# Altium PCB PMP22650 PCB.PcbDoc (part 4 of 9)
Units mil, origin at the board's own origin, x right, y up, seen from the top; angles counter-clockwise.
Board outline 11311 x 5233 mil, 8 copper layers (Layer 1, Layer 2, Layer 3, Layer 4, Layer 5, Layer 6, Layer 7, Layer 8), stack 88.6 mil thick; 633 components, 410 nets, 2503 pads, 1993 vias.
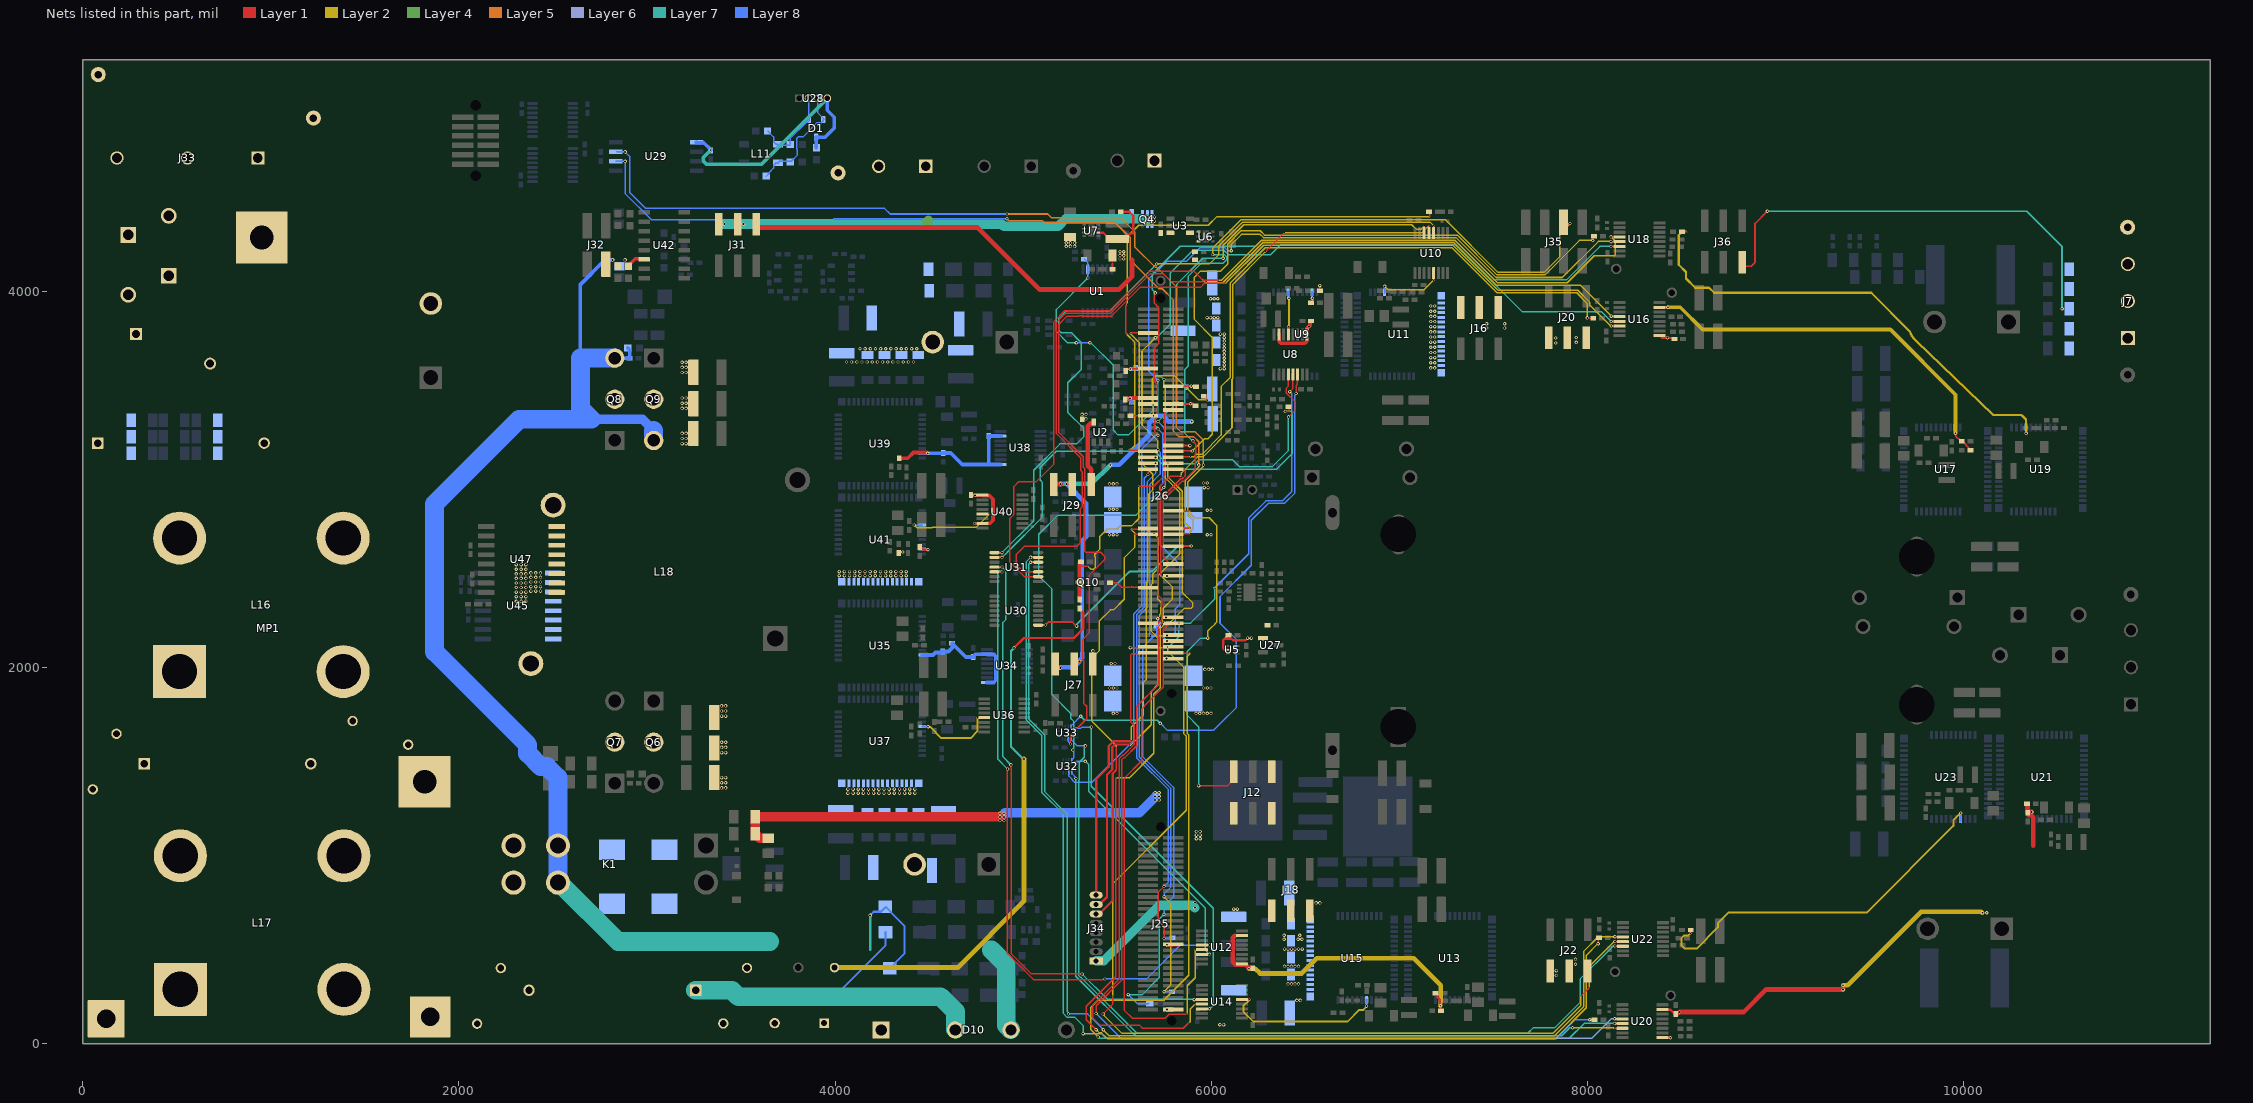
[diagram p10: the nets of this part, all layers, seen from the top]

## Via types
v1: diameter 18, hole 10, Layer 1 to Layer 8, 1759 vias
v2: diameter 8, hole 4, Layer 1 to Layer 2, 160 vias
v3: diameter 18, hole 10, Layer 1 to Layer 8, tented both sides, 34 vias
v4: diameter 8, hole 4, Layer 7 to Layer 8, 28 vias
v5: diameter 19.68, hole 7.87, Layer 1 to Layer 8, 8 vias
v6: diameter 118.11, hole 86.61, Layer 1 to Layer 8, 4 vias

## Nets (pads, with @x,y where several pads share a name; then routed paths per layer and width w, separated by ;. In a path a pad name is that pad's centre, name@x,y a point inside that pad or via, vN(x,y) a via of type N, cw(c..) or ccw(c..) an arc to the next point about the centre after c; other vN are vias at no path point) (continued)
5V_H_PFC_2: C185.1 C188.1 R113.2 U40.1 U40.7 U41.51 | length 430.8
  Layer 1 w8: R113.2@4337.63,2609.04 4337.63,2612.98 4340.44,2615.79 4358.21,2615.79 v1@4360,2614 ; v1@4493,2626 v1@4495,2624
  Layer 1 w12: C188.1@4448.27,2642.28 4454.08,2636.47 4458.02,2636.47 4466.89,2627.6 v1(4493.27,2627.6) ; v1(4741,2767) 4741.25,2767.25 4778.25,2767.25 U40.7@4779,2768
  Layer 1 w20: C185.1@4724,2918 4724.5,2917.5 U40.1@4782.7,2917.5 4784.13,2916.07 4819.48,2916.07 4839.5,2896.05 4839.5,2783.92 4824.51,2768.93 U40.7@4804.2,2768.93
  Layer 8 w12: U41.51@4463.27,2632.6 4468.27,2627.6 v1(4493.27,2627.6)
  other v1: 4359.1,2615.79 4744,2917
5V_L_A: C40.1 C43.1 R27.2 U8.1 U8.7 U9.51 | length 404.9
  Layer 1 w10: C43.1@6530,3941 6530.19,3941 6537,3947.81 v1(6537,3965) ; v1(6576,4032) 6576,4007 R27.2@6578,4005
  Layer 1 w20: U8.7@6358.98,3772.34 6360.41,3770.91 6360.41,3735.56 6370.62,3725.34 6374.48,3725.34 6374.72,3725.09 6497.08,3725.09 6507.55,3735.56 6507.55,3770.91 U8.1@6508.98,3772.34 6508.98,3805.31 v1@6517.27,3813.6 ; v1(6519.09,3814.57) 6525.14,3820.62 6525.14,3841.79 6526.95,3843.6 C40.1@6530.89,3843.6
  Layer 8 w10: v1@6517.94,3815.71 v1(6519.09,3814.57) ; U9.51@6536.03,3998.97 U9.51@6536.03,3997.68 ; v1(6537,3965) 6536.03,3965.97 U9.51@6536.03,3997.68 ; U9.51@6537.83,3999.48 U9.51@6536.03,3997.68
5V_L_B: C62.1 C65.1 R37.2 U12.1 U12.7 U13.51 | length 1671.1
  Layer 1 w12: 6126.56,576.05 U12.7@6162.57,576.05 ; R37.2@7195.89,269 7201.7,263.19 7201.7,249.3 7214.13,236.87 7214.13,213.43 7215.85,211.7 7215.85,204.15 7218.15,201.85 7218.15,178.15 7218,178 C65.1@7217,177
  Layer 1 w25: 6126.56,576.05 6123.68,576.05 6113.07,565.44 6113.07,436.65 6128.56,421.16 6182.02,421.16 6197.51,405.67 6219.95,405.67 6220.64,404.98 C62.1@6220.64,402.42
  Layer 2 w20: v1@7217.49,202.49 7218.5,203.5 7218.5,227.5 7220,229
  Layer 2 w25: v1(6200,400) 6234,400 6258.9,375.1 6480.55,375.1 6560.45,455 7075,455 7219,311 7219,230 7220,229
  Layer 8 w12: v1(7217,203) 7217.54,203.54 7217.54,233.46 U13.51@7217,234
5V_L_C: C84.1 C87.1 R47.2 U16.1 U16.7 U17.51 | length 2225.7
  Layer 1 w10: v1(9956,3247) 9957.53,3245.47 9957.53,3231.78 9983.31,3206 C87.1@9989,3206 ; C87.1@9989.65,3203.6 9993.58,3203.6 10026.14,3171.04 10026.14,3163.41 10032.95,3156.6 R47.2@10036.89,3156.6
  Layer 1 w12: U16.1@8382,3769 8396,3755 v1(8425,3755) 8426.62,3755 v1@8427,3754.62 ; U16.7@8382.3,3916.5 8382.55,3916.75 8424.75,3916.75 v1@8426,3918 ; v1@8427,3756 v1@8427,3754.62 ; C84.1@8463,3747 8456.19,3753.81 8427.81,3753.81 v1@8427,3754.62
  Layer 2 w20: v1(8427,3917) 8493,3917 8612,3798 9609.99,3798 9956,3451.99 v1(9956,3247)
  Layer 8 w12: U17.51@9954.86,3278.02 U17.51@9955.44,3277.44 ; v1(9956,3247) 9955.43,3247.57 U17.51@9955.43,3277.43 ; U17.51@9956,3278 U17.51@9955.44,3277.44 ; U17.51@9956.73,3276.15 U17.51@9955.44,3277.44
5V_L_D: C106.1 C109.1 R57.2 U20.1 U20.7 U21.51 | length 2270.7
  Layer 1 w12: U20.1@8393,33 8393.25,33.25 8440.75,33.25 v1(8441,33) ; U20.7@8398.3,183.5 8400.37,181.43 8441.37,181.43 8443.43,179.37 8443.94,179.37 C106.1@8461,162.32
  Layer 1 w25: C106.1@8468,160.38 8468,162.94 8468.69,163.63 8482.99,163.63 8486.17,166.81 8486.81,166.81 8490,170 8831,170 8951,290 v1@9360.26,290 ; C109.1@10339,1229.36 R57.2@10339,1275 ; C109.1@10339.27,1229.22 10339.27,1226.66 10350.2,1215.72 10358.53,1215.72 10369.08,1205.18 10369.08,1053.08 ; C109.1@10339.27,1229.36 10339.96,1230.05 10350.95,1230.05 10353.9,1233 v3(10361,1233)
  Layer 2 w25: v1(9359,312) 9382.26,312 9773.26,703 10093,703 v1@10098,698
  Layer 8 w10: v3@10363.1,1232.86 10364.6,1231.36 10364.6,1197.36 U21.51@10366.1,1195.86
  other v1: 8489,170 9359,289 10099.24,697.61 10122.24,697.61
5V_L_PFC_1: C148.1 C151.1 R98.2 U34.1 U34.7 U35.51 | length 657.6
  Layer 8 w20: U35.51@4463.12,2067.7 4519.69,2067.7 4533.13,2081.13 4569.46,2081.13 4571.27,2082.95 C151.1@4571.27,2086.88 4603.18,2086.88 4621.89,2105.59 R98.2@4621.89,2130.02 4625.83,2130.02 4627.64,2128.21 4627.64,2124.28 4694.41,2057.5 C148.1@4735.27,2057.5 4735.27,2061.44 4745.43,2071.6 4806.47,2071.6 U34.7@4806.97,2072.1 4808.4,2070.67 4843.75,2070.67 4854.21,2060.21 4854.21,1933.86 4842.5,1922.14 U34.1@4806.97,1922.1 U34.1@4806.97,1922.1
5V_L_PFC_2: C170.1 C173.1 R108.2 U38.1 U38.7 U39.51 | length 824.4
  Layer 1 w20: R108.2@4341.27,3114.22 4386.22,3114.22 4417,3145 4487.31,3145 v1(4492.12,3140.19)
  Layer 8 w20: U39.51@4463.12,3140.19 v1(4492.12,3140.19) 4572.83,3140.19 4574.65,3142 C173.1@4574.65,3142.51 4614.49,3142.51 4675.9,3081.1 4820.9,3081.1 ; U38.1@4878.97,3081.1 4820.9,3081.1 ; U38.7@4878.97,3231.1 4878.28,3231.79 4817.16,3231.79 C170.1@4816.47,3232.48 4816.47,3085.53 4820.9,3081.1
5V_PRI: C25.2 C26.2 C32.1 C33.2 C34.2 C37.1 C136.1 J12.5 J16.5 J18.5 J20.5 J22.5 J25.158 J25.180 J26.48 J26.84 J26.98 J26.112 J27.5 J29.5 J31.5 L2.2 R23.2 R25.2 U2.5 U3.3 U3.4 U5.2 U6.4 U6.6 U7.6 U27.1 | length 3606.2
  Layer 1 w10: v1(5758.27,2267.6) 5758.77,2268.1 5796.77,2268.1 J26.98@5797.27,2268.6 ; J26.112@5823.27,2047.6 J26.112@5823.53,2047.86
  Layer 1 w12: U7.6@5398.27,4314.6 5399.35,4313.52 5425.67,4313.52 5458.93,4280.26 L2.2@5500.27,4280.26 5541.61,4280.26 5569.9,4308.55 5584.5,4308.55 5584.5,4404.09 5564.06,4424.53 R23.2@5518.16,4424.53 ; R25.2@5474.83,4119.16 5474.83,4148.97 ; v1(5762,2050) 5762.94,2049.06 5812.94,2049.06 J26.112@5815,2047 ; v1(5763.27,2487.6) 5764,2488.33 5802.53,2488.33 J26.84@5803.27,2487.6 ; J26.48@5843.27,3182.6 5843.57,3182.29 5886.89,3182.29 5886.89,3181 v1(5886,3181) ; U5.2@6088.2,2095.29 6069.95,2095.29 6062.92,2102.32 6062.92,2147.95 6068.07,2153.1 ; C37.1@6092.2,2173.29 6088.27,2173.29 6068.07,2153.1 ; v1(6192.91,2157.72) 6181.18,2146 6115,2146 6107.9,2153.1 6068.07,2153.1
  Layer 1 w20: v1(5763.27,182.6) 5763.56,182.89 5797.11,182.89 J25.180@5797.27,183.05 ; v1(5763.27,527.6) J25.158@5828.27,527.6
  Layer 1 w25: J31.5@3577,4356 3577,4352.09 3588.49,4340.6 4757.4,4340.6 5087,4011 5506.67,4011 5578.27,4082.6 5578.27,4167.6 ; J29.5@5361.76,2978.64 5361.76,3055.4 5343.08,3074.08 5343.08,3284.21 5358.41,3299.55 U2.5@5375.18,3299.55
  Layer 5 w20: v1(5763.27,182.6) 5793.27,182.6 ; v1(5763.27,527.6) 5788.27,527.6
  other v1: 7834,364 7834,390 5920.2,1091.15 5940.27,1091.13 5920.2,1110.36 5940.27,1110.36 5920.2,1129.6 5940.27,1129.6 5370,2090 6212.59,2157.72 5333.27,3323.6 5313.27,3347.6 5333.27,3347.6 7830.73,3726.77 7830.73,3753.14 7559.27,3806.6 7559.27,3829.12 5514.27,4173.15 5534.34,4173.13 5514.27,4192.36 5534.34,4192.36 5514.27,4211.6 5534.34,4211.6
12V_PRI: C31.1 C214.1 J12.1 J12.2 J15.1 Q4.4 R17.2 R157.2 R158.2 U7.2 U7.3 | length 2338.5
  Layer 1 w50: C214.1@3644.27,1094.6 3597.57,1094.6 3585.76,1106.41 3574.93,1106.41 3574.34,1107 R158.2@3574.34,1117.83 R157.2@3574.34,1207.83 v1@4877.04,1207.83
  Layer 8 w50: 4886.92,1213.6 4901.61,1228.29 5616.23,1228.29 v1@5704.31,1316.36
  other v1: 4876.42,1188.15 4897.49,1188.13 4876.42,1207.36 4897.49,1207.36 4876.42,1226.6 4897.49,1226.6 5701.31,1297.15 5722.38,1297.13 5701.31,1316.36 5722.38,1316.36 5701.31,1335.6 5722.38,1335.6 5228.27,4240.67 5250.77,4240.67 5273.27,4240.67 5228.27,4258.85 5250.77,4258.85 5273.27,4258.85
12V_SW: J16.1 J16.3 J18.1 J18.3 J20.1 J20.3 J22.1 J22.3 J27.1 J27.3 J29.1 J29.3 J31.1 J31.3 J34.1 Q4.1 Q4.2 Q4.5 Q4.6 | length 5058.7
  Layer 1 w10: v1(5230,2978) 5267.87,2978 J29.3@5268.27,2977.6
  Layer 1 w20: J27.1@5173.27,2002.6 5177.5,1998.36 v1(5196.98,1998.36) ; J27.3@5273.27,2032.6 5275.11,2034.44 v1(5299.26,2034.44)
  Layer 1 w25: J29.1@5173.27,2977.6 v1(5198.27,2977.6)
  Layer 7 w25: v1(5230,2978) 5362.67,2978 v1(5462.27,3077.6)
  Layer 7 w50: 3399.19,4358.1 3513,4358.1 4886.9,4358.1 4896.91,4348.1 5186.64,4348.1 5226.14,4387.6 5649.48,4387.6 v1@5659.3,4377.78 ; J34.1@5387.63,441.44 5389.13,442.94 5427.92,442.94 5722.98,738 5898.87,738 v1(5912.27,724.6)
  Layer 8 w20: 5313.06,2078.24 5313.06,2675.06
  Layer 8 w25: v1@5198.27,2002.6 5267.42,2002.6 v1(5299.26,2034.44) ; v1(5198.27,2977.6) 5198.67,2978 v1(5230,2978) 5333.37,2874.63 5333.37,2695.37 5313.06,2675.06 ; v1@5298.27,2037.6 5313.06,2052.39 5313.06,2078.24 ; v1@5465.16,3079.49 5509.49,3079.49 5669.77,3239.77 5669.77,3301.77 5708,3340 5743.45,3340 5774.45,3309 v1(5896,3309)
  other v1: 7936,424 7936,450 6557,750 6576.69,750 5912.27,751.98 7939.73,3729.77 7939.73,3756.14 7464.27,3806.6 7464.27,3829.12 3411,4359 3513,4359 5659.3,4374.78 5678.53,4374.78 5697.77,4374.78 5659.3,4395.85 5678.53,4395.85 5697.77,4395.85
12VBatt-: C138.1 C140.2 D1.3 U28.4 U29.5 | length 1325.9
  Layer 7 w20: v1(3338.27,4752.6) 3298.27,4712.6 3298.27,4694.31 3315.48,4677.1 3608.92,4677.1 3958.27,5026.45 U28.4@3958.27,5027.6
  Layer 8 w20: U29.5@3263.27,4792.6 3264.08,4791.79 3301.64,4791.79 3338.27,4755.16 v1(3338.27,4752.6) C140.2@3338.27,4751.22 ; D1.3@3898.27,4817.6 3898.99,4816.88 3898.99,4765.81 C138.1@3899.7,4765.09 ; D1.3@3898.27,4820.35 3946.02,4820.35 3994.98,4869.31 3994.98,4927.21 3958.27,4963.93 U28.4@3958.27,5027.6
AC_L: C220.1 C222.2 D4.2 D6.2 D10.2 L17.1 U45.1 U45.2 U45.3 U45.4 U47.1 U47.2 U47.3 U47.4 | length 3747.3
  Layer 7 w100: C220.1@3258.09,285.63 3451.13,285.63 3485.25,251.51 4560.49,251.51 4639.97,172.03 ; D10.2@4639.97,78 4639.97,172.03 ; 4641,171 4639.97,172.03
  Layer 8 w8: C220.1@3258.09,285.63 3285.12,258.6 D6.2@4291.08,258.6
  Layer 8 w10: C220.1@3258.09,285.63 4028.63,285.63 4267.65,524.65 D4.2@4267.65,594.8
  other v1: 2304.27,2353.97 2330.27,2353.97 2355.27,2353.97 2304.27,2378.24 2330.27,2378.24 2355.27,2378.24 2304.27,2402.51 2330.27,2402.51 2355.27,2402.51 2382.27,2407.6 2408.27,2407.6 2433.27,2407.6 2304.27,2426.79 2330.27,2426.79 2355.27,2426.79 2382.27,2431.87 2408.27,2431.87 2433.27,2431.87 2304.27,2451.06 2330.27,2451.06 2355.27,2451.06 2382.27,2456.15 2408.27,2456.15 2433.27,2456.15 2304.27,2475.33 2330.27,2475.33 2355.27,2475.33 2382.27,2480.42 2408.27,2480.42 2433.27,2480.42 2304.27,2499.61 2330.27,2499.61 2355.27,2499.61 2382.27,2504.69 2408.27,2504.69 2433.27,2504.69 2304.27,2523.88 2330.27,2523.88 2355.27,2523.88 2304.27,2548.15 2330.27,2548.15 2355.27,2548.15
AC_L_CON: F3.2 F4.1 J33.3 TP7.1
AC_L_EMI: C219.1 C221.2 L16.1 L17.4
AC_L_F: C218.1 F3.1 F4.2 L16.4 R170.1 R173.2 R174.2 R175.2
AC_L_Sense_1: L18.2 U45.5 U45.6 U45.7 U45.8
AC_L_Sense_2: L18.3 U47.5 U47.6 U47.7 U47.8
AC_N: C197.2 C199.1 C200.1 C201.1 D5.2 D7.2 D10.3 J32.1 K1.3 Q6.2 Q7.2 Q8.3 Q9.3 R122.1 R160.2 R165.2 U42.14 | length 7508.1
  Layer 1 w20: C200.1@2893.2,4142.78 2905.45,4142.78 2937.27,4174.6 U42.14@2955.97,4174.6
  Layer 1 w100: K1.3@2520.92,1059.95 K1.3@2526.27,1054.6 ; Q9.3@3034.76,3209.15 Q9.3@3035.21,3208.7
  Layer 7 w12: v1(4185.62,683.8) 4186,683.43 4186,500
  Layer 7 w100: K1.3@2526.27,857.75 2533.83,857.75 2846.76,544.82 3652.54,544.82 ; 4829.89,499.8 4909.27,420.42 4909.27,99.73 D10.3@4932,77
  Layer 8 w10: D5.2@4269.02,728.35 4297.04,700.34 4297.04,697.39 4369.17,625.25 4369.17,481.69 4321.5,434.02 4321.5,431.06 4293.03,402.6 D7.2@4290.08,402.6
  Layer 8 w12: v1(4185.62,683.8) 4205.17,703.35 4244.02,703.35 D5.2@4263.27,722.6
  Layer 8 w20: 2645.27,3646.5 2645.27,4037.86 2776.41,4169 v1(2817,4169) ; Q8.3@2828.43,3646.5 2829.37,3645.55 2906.7,3645.55 C197.2@2907.65,3644.6 2907.65,3689.71 2897.76,3699.6 R122.1@2896.77,3699.6
  Layer 8 w50: 2703.85,3320.92 2975.45,3320.92 3034.76,3261.61
  Layer 8 w100: K1.3@2526.27,857.75 K1.3@2526.27,1054.6 2526.27,1416.42 2467.69,1475 2434.71,1475 2365,1544.71 2365,1590 1870.27,2084.73 1870.27,2871.5 2319.69,3320.92 2703.85,3320.92 2645.27,3379.5 2645.27,3646.5 Q8.3@2828.43,3646.5 ; 3034.76,3261.61 3034.76,3209.15 Q9.3@3035.21,3208.7
  other v1: 2883,4169
AC_N_CON: C218.2 J33.2 L16.3 R161.1 R162.1 R163.1 R170.2 TP6.1
AC_N_EMI: C216.1 C219.2 L16.2 L17.3
AC_N_Re: C217.1 C220.2 K1.4 L17.2 R160.1 R165.1
ACTIVE_EMI_INJ_PD_LEVEL: J26.9 J34.8 | length 3312.3
  Layer 1 w8: v2(5568.27,3777.6) 5572.17,3781.5 5662.31,3781.5 J26.9@5663.41,3780.41
  Layer 1 w12: J34.8@5387.63,791.44 5387.63,1407.63 5454.42,1474.42 5454.42,1584.09 5480.33,1610 v2(5574,1610)
  Layer 2 w8: v2(5568.27,3777.6) 5617.77,3728.1 5617.77,3099.26 5688,3029.03 5688,2944.63 5668,2924.63 5668,2725.51 5661.5,2719.01 5661.5,2461.39 5652.77,2452.66 5652.77,1935.94 5639,1922.17 5639,1750.01 5574,1685.01 v2(5574,1610)
ACTIVE_EMI_INJ_PD_PULSE: J26.69 J34.7 | length 2320.2
  Layer 1 w8: 5589.63,2709.54 J26.69@5635.21,2709.54 ; J26.69@5633.27,2707.6 J26.69@5635.21,2709.54 ; v2(5694.23,2713.14) 5638.81,2713.14 J26.69@5635.21,2709.54
  Layer 1 w12: J34.7@5387.63,741.44 5404.63,741.44 5444.85,781.65 5444.85,1431.64 5472.71,1459.5 5472.71,1577.63 5487.58,1592.5 5561.5,1592.5 v2(5565,1589)
  Layer 2 w8: v2(5565,1589) 5572.09,1589 5680.27,1697.18 5680.27,1874.34 5715.5,1909.58 5715.5,2159.31 5679.77,2195.04 5679.77,2441.48 5689,2450.71 5689,2500.28 5716.77,2528.04 5716.77,2690.6 v2(5694.23,2713.14)
ACTIVE_EMI_INJ_PU_PULSE: J26.67 J34.6 | length 2339.9
  Layer 1 w8: 5490.05,1452.09 5494,1456.04 v2(5494,1577) ; v2(5573.27,2735.6) 5636.27,2735.6 J26.67@5643.27,2742.6
  Layer 1 w12: J34.6@5387.63,691.44 5404.63,691.44 5476.27,763.07 5476.27,1438.31 5490.05,1452.09
  Layer 2 w8: v2(5494,1577) 5494,1587 5363,1718 5363,2050 5405.27,2092.27 5405.27,2249.85 5463.31,2307.89 5479.73,2307.89 5536.77,2364.94 5536.77,2515.26 5536,2516.03 5536,2584 5594,2642 5594,2714.87 v2(5573.27,2735.6)
ACTIVE_EMI_RESET: J26.87 R176.2 | length 176.7
  Layer 1 w8: R176.2@5461.89,2452.6 5498.27,2452.6 5523.27,2427.6 v2(5573.27,2427.6) J26.87@5628.27,2427.6
ACTIVE_EMI_SENSE: C233.1 J26.36 Q10.3 R177.1 | length 1540.4
  Layer 1 w8: 5297.27,2543.6 5298.27,2542.6 5299.87,2541 v2(5342,2541) ; v2(5614,2965) 5693.67,2965 5753,3024.33 5753,3365.41 5757.69,3370.1 J26.36@5820.77,3370.1
  Layer 1 w20: Q10.3@5297.35,2454.46 5297.35,2370.01 5301.18,2366.19 R177.1@5301.18,2362.26 ; 5298.27,2384.6 5298.27,2542.6 5298.27,2559.26 C233.1@5302.04,2563.03
  Layer 2 w8: v2(5342,2541) 5359.5,2523.5 5373.59,2523.5 5381.5,2531.41 5381.5,2591.41 5380.5,2592.41 5380.5,2603.59 5406,2629.09 5406,2696.34 5446.26,2736.6 5497,2736.6 5514.5,2754.1 5575.93,2754.1 5614,2792.17 v2(5614,2965)
BATT_RTN: J7.1 J7.2 J7.3 J36.6 R1.2 R2.2 R3.2 R4.2 R5.2 TP2.1 | length 2346.4
  Layer 1 w10: J36.6@8827,4135.07 8870.74,4135.07 8890.77,4155.1 8890.77,4362.1 v1(8956.18,4427.52)
  Layer 7 w10: v1(8956.18,4427.52) 10334.35,4427.52 10523,4238.87 v1(10523,3909)
CAN_RX: J26.70 U29.3 | length 4978.8
  Layer 1 w8: J26.70@5808.27,2707.6 5813.27,2712.6 v2(5888.27,2712.6)
  Layer 5 w8: v1(4913.27,4412.6) 5130.1,4412.6 5149.7,4393 5518,4393 5592,4319 5592,4238.84 5702.34,4128.5 5710.76,4128.5 5814,4025.26 5814,3278 5838,3254 5914,3254 5958,3210 v1(5958,3078)
  Layer 2 w8: v2(5888.27,2712.6) 5888.27,2723.51 5903,2738.24 5903,2785 ; 5902.82,2786.09 5874.77,2814.14 5874.77,2987.91 5958,3071.15 v1(5958,3078)
  Layer 8 w8: U29.3@2838.27,4742.6 2838.77,4743.1 v1@2882.77,4743.1 ; v1@2883.27,4737.6 2888.27,4737.6 2908.27,4717.6 2908.27,4527.6 2993.27,4442.6 4263.02,4442.6 4293.02,4412.6 v1(4913.27,4412.6)
  other v1: 2883.27,4742.6
CAN_TX: J26.68 U29.2 | length 4873.1
  Layer 1 w8: J26.68@5813.27,2742.6 v2(5888.27,2742.6)
  Layer 5 w8: v1(4913.27,4387.6) 4923.87,4377 5102,4377 5113,4366 5489,4366 5569,4286 5569,4168.34 5722.02,4015.32 5738.68,4015.32 5798.27,3955.73 5798.27,3258.73 5829.4,3227.6 5907.34,3227.6 5933,3201.94 v1(5933,3079)
  Layer 2 w8: v2(5888.27,2742.6) 5861.27,2769.6 5861.27,2996.51 5933,3068.24 v1(5933,3079)
  Layer 8 w8: U29.2@2833.77,4693.1 2882.77,4693.1 v1(2883.27,4692.6) 2883.27,4521.9 3022.16,4383 3988.79,4383 3993.39,4387.6 v1(4913.27,4387.6)
CANH_BUS: D1.2 L11.4 R85.2 R86.1 U28.3 | length 629.9
  Layer 8 w8: R85.2@3634.69,4614.6 3649.39,4629.3 3649.39,4633.72 3672.7,4657.03 3672.7,4670.67 3684.63,4682.6 L11.4@3698.27,4682.6 ; L11.4@3695.27,4684.39 3703.48,4692.6 3766.19,4692.6 3799.54,4725.95 3799.54,4756 3795.58,4759.96 3795.58,4814.91 3803.27,4822.6 3828.27,4822.6 3903.27,4897.6 D1.2@3926.3,4897.6 ; U28.3@3908.27,5027.6 3908.27,4950.12 3938.27,4920.12 D1.2@3938.27,4912.6 ; D1.2@3928.27,4897.6 D1.2@3926.3,4897.6 ; D1.2@3935.67,4914.84 3935.67,4906.97 D1.2@3926.3,4897.6
CANL_BUS: D1.1 L11.3 R87.2 R88.2 U28.2 | length 458
  Layer 8 w8: R88.2@3642.19,4852.6 3672.7,4822.09 3672.7,4796.53 3686.41,4782.81 L11.3@3695.27,4782.81 ; L11.3@3693.27,4782.6 3697.27,4778.6 3761.77,4778.6 R87.2@3762.21,4778.6 ; R87.2@3761.77,4782.6 3761.77,4816.1 3846.19,4900.52 3853.2,4900.52 3863.27,4910.58 D1.1@3863.27,4917.6 ; U28.2@3858.27,5027.6 3859.57,5026.3 D1.1@3859.57,4918.9
CHASSISHP: C234.2 R177.2 | length 3057.5
  Layer 1 w8: R177.2@5301.18,2315.01 R177.2@5304.56,2311.63
  Layer 1 w12: v1@4951,2106 5004,2159 5269.29,2159 5319.5,2209.21 5319.5,2292.75 5306.99,2305.26 5306.99,2309.2 R177.2@5304.56,2311.63
  Layer 2 w25: C234.2@3996.83,406.24 4651.24,406.24 5003.67,758.67 v1@5003.67,1515.67
  Layer 7 w12: v1(4950.5,2106.05) 4950.5,2104.43 4935,2088.93 4935,1580 v1@4999,1516
  other v1: 5004.5,1515.05
CLLLC_FAULTn: J26.74 U30.8 | length 1080
  Layer 1 w10: U30.8@5083.67,2227.2 5117.87,2227.2 5134.67,2244 5259.07,2244 5281.83,2221.24 v1(5283.45,2221.24) ; J26.74@5818.27,2642.6 5823.27,2647.6 v1@5888.27,2647.6
  Layer 7 w10: v1(5283.45,2221.24) 5284.99,2222.77 5284.99,2231.89 5560.19,2507.1 5561.6,2507.1 5566.85,2512.35 5686.85,2512.35 5821.06,2646.55 5892.22,2646.55 v1(5893.27,2647.6)
  other v1: 5118.27,2227.6
CLLLC_GAN_OC_PRIM_LEG1_H: J26.99 U10.13 | length 3302.5
  Layer 1 w8: J26.99@5663.41,2237.1 5717.39,2237.1 5722.52,2242.23 5723.14,2242.23 5737,2256.09 5737,2365.04 5716,2386.04 5716,2609.17 5716.77,2609.94 5716.77,2625.26 5716,2626.03 5716,2909.91 5728.5,2922.41 5728.5,2933.59 5728.27,2933.82 5728.27,2966.31 5779.96,3018 v2@5839,3018 ; v2@5839,3018.94 v2(5840.57,3018.94) ; v2(6288,4213) v2(6389,4314) ; U10.13@7156.69,4310.9 v2(7156.69,4350.9)
  Layer 2 w8: v2(5840.57,3018.94) 5840.57,3036.07 5925.6,3121.1 5955.19,3121.1 6109.77,3275.68 6109.77,3534.68 6113.5,3538.41 6113.5,4038.5 v2(6288,4213) ; v2(6389,4314) 7119.8,4314 v2(7156.69,4350.9)
CLLLC_GAN_OC_PRIM_LEG1_L: J26.107 U8.13 | length 2095
  Layer 1 w8: v1@5573.27,2107.6 5633.27,2107.6 J26.107@5638.27,2112.6 ; v1(6417.02,3468.47) 6433.98,3485.43 U8.13@6433.98,3559.74
  Layer 7 w8: v1@5568,2106 5769,2106 5826.96,2163.96 v4(5826.96,2204.78) ; v4(5828.27,2237.6) 5889.43,2237.6 6016.77,2364.94 6016.77,2419.1 v4(6013.27,2422.6)
  Layer 8 w8: v4@5828.27,2207.6 v4(5828.27,2237.6) ; v4@6012.88,2422.21 v4(6013.27,2422.6) 6015.6,2422.6 6199,2606 6199,2796 6290,2887 6377,2887 6428.5,2938.5 6428.5,3456.98 v1(6417.02,3468.47)
  other v1: 5569.63,2107.14
CLLLC_GAN_OC_PRIM_LEG2_H: J26.109 U14.13 | length 2825.2
  Layer 1 w8: J26.109@5663.41,2079.62 5657.57,2073.78 5575.95,2073.78 5570.29,2068.11 5570.29,1908.36 5571,1907.65 5571,1898.84 cw(c5498.27,1892.6) 5571,1886.35 5571,1763.84 cw(c5498.27,1757.6) 5571,1751.35 5571,1712.92 5573.34,1710.58 5589.5,1694.42 5589.5,1591.58 5532.52,1534.6 5528.01,1534.6 5509.27,1515.85 5509.27,1511.35 5509,1511.08 5509,344 5368.27,203.27 5368.27,140.73 5408.63,100.37 5618.07,100.37 5634.44,84 5851,84 v2@5880,113 ; v2(5914,212) 5949.92,212 U14.13@5949.97,212.05
  Layer 2 w8: v2(5880,112) 5880.16,112 5884.58,116.42 ; 5885,116 5886.5,117.5 5886.5,184.5 v2(5914,212)
CLLLC_GAN_OC_PRIM_LEG2_L: J26.100 U12.13 | length 2934.5
  Layer 1 w8: J26.100@5797.27,2237.1 5783.49,2237.1 5771.34,2224.95 5765.13,2224.95 5755.18,2215 5753.18,2215 5743.5,2205.32 5743.5,1897.05 5658.32,1811.87 5658.08,1811.62 5656.88,1810.31 5630,1780.69 5630,1506.08 5536,1412.08 5536,181 5580,137 5753.61,137 5774.61,158 5783.57,158 cw(c5789.39,124) 5795.22,158 v2(5871,158)
  Layer 1 w10: v2(5914.44,500.69) 5949.31,500.69 U12.13@5950,500
  Layer 2 w10: v2@5872,158 5872,309 5914.44,351.44 v2(5914.44,500.69)
CLLLC_GAN_OC_SEC_LEG1_H: J26.104 U18.13 | length 4914.8
  Layer 1 w8: v1(5763.27,2172.6) 5828.27,2172.6 J26.104@5823.27,2177.6 ; v1@8126,4265 8126.75,4265.75 8169.45,4265.75 U18.13@8169.7,4265.5
  Layer 2 w8: v1(6106,4217) 6106,4250.11 6160.12,4304.23 6259.68,4304.23 6276.91,4287 7301.37,4287 7513.37,4075 7865.91,4075 8057.84,4266.93 8124.07,4266.93 v1(8125,4266)
  Layer 7 w8: v1(5716.27,3270.17) 5696,3290.44 5696,3336 5716.27,3356.27 v1(5716.27,3528.6)
  Layer 8 w8: v1(5716.27,3270.17) 5740.5,3245.94 5740.5,2978.54 5727,2965.04 5727,2653.87 5832,2548.87 5832,2336.68 5820.12,2324.8 5808.27,2312.95 5808.27,2187.6 5793.27,2172.6 ; v1(5716.27,3528.6) 5667.5,3577.37 5667.5,4066.5 5762.5,4161.5 5867.32,4161.5 5938.32,4232.5 6072.78,4232.5 6088.28,4217 v1(6106,4217) ; v1(5763.27,2172.6) 5792.79,2172.6
CLLLC_GAN_OC_SEC_LEG1_L: J26.106 U16.13 | length 4836.1
  Layer 1 w8: v1(5763.27,2142.6) 5768.61,2137.26 5792.93,2137.26 J26.106@5798.27,2142.6 ; v1(8126,3841) 8126.25,3841.25 8171.75,3841.25 U16.13@8172,3841
  Layer 2 w8: v1(5702.27,3754.6) 5631.27,3683.6 5631.27,3290.73 5716.27,3205.73 v1(5716.27,3160.03)
  Layer 7 w8: v4(5676.6,2170.48) 5736.39,2170.48 5763.27,2143.6 v1(5763.27,2142.6) ; v1(5702.27,3754.6) 5703.8,3756.13 5710.09,3756.13 5780.22,3826.26 5780.22,4097.22 5902.35,4219.35 6066.2,4219.35 6090.54,4195 6313,4195 6366,4248 7298,4248 7652,3894 8073,3894 v1@8125,3842
  Layer 8 w8: v4@5676.23,2169.64 5673.27,2172.6 5673.27,2976.27 5727,3030 5727,3147.13 5716.27,3157.86 v1(5716.27,3160.03)
CLLLC_GAN_OC_SEC_LEG2_H: J26.108 U22.13 | length 5338.3
  Layer 1 w8: v1(5424.27,159.6) v1@5426.33,161.67 ; v1@5426,162 5426.67,162 5476.97,212.3 v2(5476.97,256.42) ; v2(5766.97,2111.42) 5807.58,2111.42 J26.108@5808,2111 ; J26.108@5791.43,2105.28 J26.108@5797.27,2111.12 ; v2(7965,255) 8006,296 v2@8006,301 ; v1(8145,545) 8145.25,544.75 8195.25,544.75 U22.13@8196,544
  Layer 2 w8: v1(5424.27,159.6) 5430.12,150.94 5431.97,148.19 5498.48,81.69 5524.16,56 7815,56 7842,83 7965,206 7965,254 v2@7964,255 ; v2@5477,256.92 5477,853.36 5866,1242.36 5866,1637.03 5852,1651.03 5852,2004 5766.97,2089.03 v2(5766.97,2111.42) ; v2(8008,301) 8008,410.16 8143.84,546 v1@8145,546
CLLLC_GAN_OC_SEC_LEG2_L: J26.110 U20.13 | length 5392.6
  Layer 1 w8: J26.110@5808.27,2077.6 v2(5888.27,2077.6) ; v1@8143,110 v1(8144,109) 8144.25,108.75 8185.45,108.75 U20.13@8185.7,108.5
  Layer 2 w8: v1@5398.93,36.93 5359.27,76.6 5359.27,194.27 5398,233 5747,233 5879.5,365.5 5879.5,1642.62 5872.5,1649.62 5872.5,2061.83 v2(5888.27,2077.6)
  Layer 7 w8: v1(5398,37) 5399.69,37 5406.69,30 7903,30 7983.45,110.45 8142.55,110.45 v1(8144,109)
CLLLC_IPRIM: C134.1 J26.34 R80.2 | length 147.1
  Layer 1 w8: J26.34@5838.27,3402.6 5838.34,3402.53 5851.2,3402.53 ; J26.34@5849.27,3400.6 5851.2,3402.53 ; 5854.7,3403.03 5851.7,3403.03 5851.2,3402.53
  Layer 1 w12: 5854.27,3402.6 5854.7,3403.03 5888.7,3403.03 v1(5889.27,3403.6) ; v1@5888.27,3403.6 5889.03,3404.36 C134.1@5901.65,3404.36
  Layer 8 w8: R80.2@5811.13,3403.86 5811.76,3403.23 5888.9,3403.23 v1(5889.27,3403.6)
CLLLC_IPRIM_TANK: C127.1 J26.33 J26.37 R68.2 | length 698
  Layer 1 w8: C127.1@5570.2,3339.46 5625.13,3339.46 J26.37@5628.27,3342.6 ; J26.37@5659,3339 5660,3340 v2(5692,3340)
  Layer 1 w10: J26.33@5663.41,3402.46 5668.25,3397.61 J26.33@5691.67,3397.61 ; R68.2@5959.94,3437.12 5963.87,3437.12 v2@5977.12,3423.87
  Layer 2 w8: v2(5692,3340) 5691,3341 v2(5691,3397) 5684.77,3403.23 5684.77,3533.77 5704,3553 5804,3553 5933,3424 5976.87,3424 v2(5978.27,3422.6)
CLLLC_ISEC: C246.1 J26.21 R198.2 | length 248.4
  Layer 1 w8: C246.1@5548.27,3587.6 5548.67,3588 5571,3588 v1@5565.75,3588 ; v1@5565.75,3589.01 J26.21@5660.98,3589.01 ; v1@5571,3589.01 J26.21@5660.98,3589.01 ; J26.21@5663.41,3591.43 J26.21@5660.98,3589.01
  Layer 8 w20: v1@5571,3588 5572,3589 5596.46,3589 5598.27,3590.81 R198.2@5598.27,3593.98
  other v1: 5569,3588
CLLLC_ISEC_TANK: C237.1 J26.28 R180.2 | length 114.9
  Layer 1 w8: J26.28@5833.27,3497.6 5833.59,3497.27 5914.32,3497.27 C237.1@5914.65,3497.6
  Layer 8 w8: R180.2@5867,3491.62 5872.98,3497.6 v1(5893.27,3497.6) ; v1@5894.8,3496.07 v1(5893.27,3497.6) ; v1@5895,3499 5893.6,3497.6 v1(5893.27,3497.6)
CLLLC_LC_CHANGE: J12.6 J26.62 | length 2009.3
  Layer 1 w8: J26.62@5808.27,2837.6 5813.27,2832.6 v2(5888.27,2832.6) ; v1(5932.22,1373.6) 6087.07,1373.6 6122,1408.53 J12.6@6122,1459
  Layer 2 w8: v2(5888.27,2832.6) 5888.27,2819.73 5910.4,2797.6 5988.27,2797.6 6028,2757.87 6028,2242.58 6016.77,2231.35 6016.77,2229.94 6005.93,2219.1 6004.52,2219.1 5980.91,2195.49 v1(5980.91,2157.72)
  Layer 7 w8: v1(5932.22,1373.6) 5932.22,1687.08 5872.5,1746.8 5872.5,2087.99 5942.23,2157.72 5978.15,2157.72 v1@5978.27,2157.6
CLLLC_PRIM_FAULT_LEG1_H: U10.12 U31.1 | length 3942
  Layer 1 w8: U31.1@4848.27,2612.6 4848.52,2612.35 v1(4887.13,2612.35) ; v2(7181.69,4350.9) U10.12@7181.69,4310.9 7181.69,4309.17 U10.12@7182.27,4308.6
  Layer 2 w8: v1(5710,4147) 5990,4147 6038,4195 6038,4241 6166.5,4369.5 7162.37,4369.5 v2@7180.38,4351.49
  Layer 7 w8: v1(4887.13,2612.35) 5055.5,2780.72 5055.5,3050.75 5194.75,3190 5282.67,3190 5322.27,3229.6 5322.27,3271.73 5236.82,3357.18 5236.82,3515.46 5309,3587.64 5309,3727.73 5290.15,3746.58 5255.73,3781 5202.09,3781 5189.5,3793.59 5189.5,3857.5 5231,3899 5462,3899 v1(5710,4147)
CLLLC_PRIM_FAULT_LEG1_L: U8.12 U31.2 | length 2500.6
  Layer 1 w8: U31.2@4848.27,2587.6 4849.11,2586.76 v1(4887.13,2586.76) ; U8.12@6408.98,3559.74 6407.81,3558.58 6407.81,3496.07 6397,3485.26 6397,3462.32 6446.71,3412.61 6446.71,3370.71 v1(6410,3334)
  Layer 7 w8: v1(4887.13,2586.76) 4887.7,2586.76 4914.5,2613.56 4914.5,2614.01 5102,2801.51 5102,2985.23 5090.22,2997.01 5090.22,3066.38 5175.34,3151.5 5698.5,3151.5 5766,3084 5911.84,3084 5932.78,3104.94 6113.23,3104.94 6149,3069.17 6195.91,3069.17 6196.37,3069.63 6324.63,3069.63 6410,3155 v1(6410,3334)
CLLLC_PRIM_FAULT_LEG2_H: U14.12 U31.4 | length 3249.3
  Layer 1 w8: U31.4@4847.13,2535.57 4847.22,2535.48 v1@4887.13,2535.48 ; v1(4934,1484) 4934.21,1483.79 4934.21,1470.51 4935,1469.72 4935,481.09 5043.4,372.69 5312.12,372.69 v1(5312.79,372.03) ; v1(5909,236) 5948.92,236 U14.12@5949.97,237.05 5943.82,237.05 U14.12@5943.27,237.6
  Layer 7 w8: v1(4887.13,2536) 4905.63,2517.5 4905.63,2254.53 4892,2240.9 4892,1526.69 4934,1484.69 v1(4934,1484) ; v1(5312.79,372.03) 5447.22,237.6 v1@5909,237.6
CLLLC_PRIM_FAULT_LEG2_L: U12.12 U31.5 | length 3360.9
  Layer 1 w8: U31.5@4847.13,2509.98 v1@4888,2509.98 ; v1(4916.5,1462.05) 4916.03,1461.59 4916.03,480.97 5054.4,342.6 5425.58,342.6 5427.16,344.18 5432.74,344.18 v1(5434.27,345.71) ; U12.12@5948.27,527.6 5949.82,526.05 U12.12@5949.97,526.05 v1(5989.97,526.05)
  Layer 7 w8: v1@4885,2514 4872,2514 4865,2507 4865,1513.55 v1(4916.5,1462.05)
  Layer 8 w8: v1(5434.27,345.71) 5654.67,345.71 5835.01,526.05 v1(5989.97,526.05)
  other v1: 4887.13,2509.39
CLLLC_PRIM_LEG1_H: J26.49 R35.1 | length 2958.5
  Layer 1 w8: v2(5550.27,3774.9) 5546,3779.17 5546,3925.33 v2(5553.27,3932.6) ; v2(5563.27,3162.6) 5569.54,3156.33 5657.57,3156.33 J26.49@5663.41,3150.49 ; R35.1@7158.07,4425.6 7156.69,4424.22 7162.27,4418.65 v2(7162.27,4398.6)
  Layer 2 w8: v2(5550.27,3774.9) 5550.27,3773.1 5592,3731.37 5592,3180 5574.6,3162.6 v2(5563.27,3162.6) ; v2(5553.27,3932.6) 5553.27,4292.6 5613.67,4353 5983.67,4353 6029.27,4398.6 v2(7162.27,4398.6)
CLLLC_PRIM_LEG1_H_TEMP: U10.14 U32.4 | length 4744
  Layer 1 w8: U10.14@7127.27,4313.6 7131.69,4318.02 v2(7131.69,4350.9)
  Layer 2 w8: v1@6062.78,4178.42 6062.78,4246.69 6172.09,4356 7065,4356 7088.6,4332.4 7114.93,4332.4 7131.69,4349.16 v2(7131.69,4350.9)
  Layer 7 w8: v1(5264,1563) 5264,1565.71 5269.5,1571.21 5269.5,1714.12 5251.5,1732.12 5251.5,1758.5 5152.5,1857.5 5152.5,1868.7 5152.36,1868.85 5152.36,1884.17 5152.5,1884.32 5152.5,2418.37 5082.5,2488.37 5082.5,2710.53 5183.97,2812 5600.13,2812 v1(5746.77,2958.64) ; v1(5716.27,3309.6) 5815,3408.33 5815,3976.76 5814.77,3977 5814.77,3992.32 5815,3992.55 5815,4038 5954.51,4177.51 v1(6062.78,4177.51)
  Layer 8 w8: U32.4@5258.65,1507.97 5258.65,1515.72 5258.72,1515.78 5262.64,1515.78 5269.5,1522.64 5269.5,1557.5 v1(5264,1563) ; v1(5716.27,3309.6) 5755,3270.87 5755,2968.33 5746.77,2960.1 v1(5746.77,2958.64)
CLLLC_PRIM_LEG1_L: J26.51 R30.1 | length 1129.6
  Layer 1 w8: J26.51@5668.27,3117.6 5668.96,3118.3 5702.57,3118.3 v1(5703.27,3117.6) ; v1@6391.27,3361.6 6392.27,3362.6 v1(6393.27,3362.6) 6412.89,3362.6 6412.89,3385.11 R30.1@6409,3389
  Layer 7 w8: v1@5703.76,3118.99 5767.09,3055.67 6345.67,3055.67 6430,3140 6430,3357.91 6425.31,3362.6 v1(6393.27,3362.6)
CLLLC_PRIM_LEG1_L_TEMP: U8.14 U33.4 | length 3014.5
  Layer 1 w8: v1(6450.73,3458.1) 6450.73,3499.53 6456.82,3505.62 6456.82,3557.58 U8.14@6458.98,3559.74
  Layer 7 w8: v1(5305.37,1742.6) 5326.94,1721.03 5712.09,1721.03 v1(5728.39,1704.73)
  Layer 8 w8: U33.4@5255.8,1685.69 5255.8,1693.44 5304.95,1742.6 v1(5305.37,1742.6) ; v1(5728.39,1704.73) 5729.05,1704.73 5764.78,1669 5920.33,1669 5921.67,1667.66 5941.95,1667.66 6011.57,1667.66 6049.89,1705.98 6133,1789.09 6133,2149.74 6045.95,2236.79 6045.95,2378.79 6212.5,2545.34 6212.5,2783.91 6302.09,2873.5 6387.5,2873.5 6444,2930 6444,3448.66 6450.73,3455.39 v1(6450.73,3458.1)
CLLLC_PRIM_LEG2_H: J26.53 R45.1 | length 3039.3
  Layer 1 w8: J26.53@5668.27,3092.6 5673.32,3087.55 5703.22,3087.55 v1(5703.27,3087.6)
  Layer 2 w8: v1(5748.27,277.54) 5783.27,312.54 5783.27,747.6 v1(5748.27,782.6)
  Layer 8 w8: v1(5703.27,3087.6) 5703.27,3033.36 5658.27,2988.36 5658.27,2319.08 5616.77,2277.58 5616.77,1526.29 5785.27,1357.78 5785.27,834.78 5748.27,797.78 v1(5748.27,782.6) ; v1(5748.27,277.54) 5748.65,277.92 5789.72,277.92 R45.1@5790.1,278.3
CLLLC_PRIM_LEG2_H_TEMP: U14.14 U33.5 | length 1904.2
  Layer 1 w8: U14.14@5948.27,187.6 5948.82,187.05 U14.14@5949.97,187.05 v1(5989.97,187.05)
  Layer 7 w8: v1(5362,1685) 5362,1370 6010.27,721.73 6010.27,204.27 5998.05,192.05 5997.67,192.05 5992.67,187.05 v1(5989.97,187.05)
  Layer 8 w8: U33.5@5279.42,1677.82 5304.72,1677.82 5311.9,1685 v1(5362,1685)
CLLLC_PRIM_LEG2_L: J26.55 R40.1 | length 2673
  Layer 1 w8: v1(5663.27,3027.6) J26.55@5663.27,3057.6 ; v1(5748.27,561) 5748.27,623.53 5717,654.8 5717,806.33 v1(5748.27,837.6)
  Layer 8 w8: v1(5663.27,3027.6) 5643.27,3007.6 5643.27,2323.18 5603.27,2283.18 5603.27,1520.7 5771.77,1352.19 5771.77,861.1 v1(5748.27,837.6) ; v1(5748.27,561) 5790.67,561 R40.1@5793.33,563.66
CLLLC_PRIM_LEG2_L_TEMP: U12.14 U32.5 | length 1389.5
  Layer 1 w8: U12.14@5949.97,476.05 v1(5989.97,476.05)
  Layer 7 w8: v1(5329.27,1502.6) 5331.43,1502.6 5347.77,1486.26 5347.77,1342.64 5967,723.41 5967,499.01 v1(5989.97,476.05)
  Layer 8 w8: U32.5@5282.28,1500.1 5284.78,1502.6 v1(5329.27,1502.6)
CLLLC_SEC_FAULT_LEG1_H: U18.12 U31.10 | length 5271.4
  Layer 1 w8: U31.10@5075.65,2509.98 4999.72,2509.98 4975.6,2534.1 4964.77,2544.94 4964.77,2547.42 4964,2548.18 4964,2603.33 5006.67,2646 5285,2646 5304,2665 5304,2847 5314.26,2857.26 5314.26,3041.5 5305,3050.76 5305,3116.46 5176.27,3245.2 5176.27,3835.27 5226.7,3885.7 5465.61,3885.7 5673.91,4094 5745.27,4094 5785.76,4053.5 5954.59,4053.5 5962.09,4061 v2(6039,4061) ; v1(8125,4291) 8125.25,4290.75 8167.75,4290.75 U18.12@8168,4291
  Layer 2 w8: v2(6039,4061) 6054.82,4061 6267.32,4273.5 7295.78,4273.5 7521.78,4047.5 7892.59,4047.5 8035.59,4190.5 8142.81,4190.5 8147.5,4195.19 8147.5,4269.66 8126.16,4291 v1(8125,4291)
CLLLC_SEC_FAULT_LEG1_L: U16.12 U31.9 | length 5005.4
  Layer 1 w8: U31.9@5079.41,2484.39 5006.22,2484.39 4970.01,2520.6 4927,2563.61 4927,2792 4950,2815 4950,2964 4976,2990 5069.82,2990 5162.77,3082.94 5162.77,3840.86 5221.11,3899.2 5460.02,3899.2 5668.32,4107.5 5908.5,4107.5 v2(5949,4067) ; v1(8126,3870) 8127.75,3868.25 8163.75,3868.25 U16.12@8167,3865
  Layer 2 w8: v2(5949,4067) 5968.5,4047.5 6060.41,4047.5 6272.91,4260 6308.09,4260 7290.18,4260 7516.18,4034 7962,4034 8124,3872 v1@8124,3870
CLLLC_SEC_FAULT_LEG2_H: U22.12 U31.12 | length 5916.7
  Layer 1 w8: v1(5039.41,2561.17) 5076.83,2561.17 U31.12@5078.27,2562.6 ; v1(8145,570) 8145.25,569.75 8188.75,569.75 U22.12@8189,570
  Layer 2 w8: v1@5428.18,71.6 5457.28,42.5 7823.41,42.5 7979.27,198.36 7979.27,492.27 8057,570 v1@8144,570
  Layer 7 w8: v1(5039.41,2561.17) 5029,2550.76 5029,1789.16 5028.5,1788.66 5028.5,1729.02 5036.26,1721.26 5113,1644.52 5113,1341.6 5233,1221.6 5233,173.82 5238.56,168.26 5238.56,161.51 v1(5240.47,159.6)
  Layer 8 w8: v1(5240.47,159.6) 5342.27,159.6 v1(5426.27,75.6)
CLLLC_SEC_FAULT_LEG2_L: U20.12 U31.13 | length 5652.4
  Layer 1 w8: v1(5039.41,2586.76) 5077.43,2586.76 U31.13@5078.27,2587.6 ; v1@8143,134 8143.25,133.75 8185.45,133.75 U20.12@8185.7,133.5
  Layer 6 w8: v1@5319,56 5320,55 5389.84,55 5390.34,55.5 5405.66,55.5 5406.16,55 5414,55 5438,31 8025,31 8129,135 8143,135 v1(8144,134)
  Layer 7 w8: v1@5038.27,2586.19 5015,2562.92 5015,1723.43 5030.67,1707.76 5099.5,1638.93 5099.5,1336.01 5213.16,1222.34 5213.16,162.16 5221.97,153.35 5221.97,151.94 5232.91,141 5275,141 5318,98 v1(5318,55)
CLLLC_SEC_LEG1_H: J26.50 R55.1 | length 3591
  Layer 1 w8: J26.50@5803.27,3152.6 v1(5898.27,3152.6) ; v1(8028,4272) 8028,4288 R55.1@8034,4294
  Layer 2 w8: v1(5898.27,3152.6) 5963.17,3217.5 5981.66,3217.5 6005.27,3241.1 6005.27,3756.73 5910,3852 5910,4076 5943,4109 6049.42,4109 6087.5,4147.08 6087.5,4252.32 6158.18,4323 6260,4323 6282.5,4300.5 7306.96,4300.5 7518.96,4088.5 7773.61,4088.5 7957.11,4272 8025,4272 v1@8026,4271
CLLLC_SEC_LEG1_H_TEMP: U18.14 U32.10 | length 5775.9
  Layer 1 w8: v1(5702,3993) 5695.84,3986.84 5695.84,3939.16 5720.77,3914.23 5720.77,3725.48 5701.27,3705.98 5701.27,3704.56 5696.53,3699.82 5696.53,3522.17 5712.03,3506.67 5712.03,3334.03 5697.77,3319.77 5697.77,3301.94 5698.77,3300.94 5698.77,3278.83 5697.77,3277.83 5697.77,3255.1 v1(5716.27,3236.6) ; v1@8125.75,4240.25 8169.45,4240.25 U18.14@8169.7,4240.5
  Layer 7 w8: v1(5702,3993) 5702,3994.99 5686,4010.99 5686,4092 5717.88,4123.88 5835,4241 6235,4241 6265,4271 7294.09,4271 7503.09,4062 7888,4062 8066,4240 8122,4240 v1@8123,4241
  Layer 8 w8: U32.10@5242.91,1444.98 5242.91,1424.49 5255.8,1411.6 5255.8,1410.47 5260.92,1405.35 5260.92,1403.94 5272.85,1392 5365.61,1392 5588.27,1614.66 5588.27,2287.27 5629.27,2328.27 5629.27,3160.23 5704.81,3235.77 5715.44,3235.77 v1(5716.27,3236.6)
  other v1: 8125,4240
CLLLC_SEC_LEG1_L: J26.52 R50.1 | length 3325
  Layer 1 w8: J26.52@5813.27,3117.6 5818.27,3122.6 v2(5888.27,3122.6) ; v1@7999,3859 7999.5,3859.5 8029.88,3859.5 R50.1@8030.38,3859
  Layer 2 w8: v2(5888.27,3122.6) 5908.01,3122.6 5920.01,3134.6 5949.6,3134.6 6052,3237 6052,3496 6100,3544 6100,4046.09 6286.91,4233 7279,4233 7518.5,3993.5 7942.5,3993.5 7999,3937 v1(7999,3860)
CLLLC_SEC_LEG1_L_TEMP: U16.14 U33.10 | length 5851.7
  Layer 1 w8: v1(5251,1595) 5251,1642.98 5337.37,1729.34 5337.37,1795.06 5320.5,1811.92 5320.5,2040.78 5316,2045.28 5316,2151.03 5349.77,2184.8 5349.77,2491.26 5432.5,2573.99 5432.5,2593.08 5411.58,2614 5332.45,2614 5327.76,2618.69 5327.76,3058.28 5318.5,3067.55 5318.5,3122.06 5189.77,3250.79 5189.77,3826.77 5233.1,3870.1 5294.6,3870.1 5295.6,3871.1 5310.93,3871.1 5311.93,3870.1 5469.1,3870.1 5620.93,4021.93 5942.11,4021.93 5965.18,4045 v2(6077,4045) ; v1(8126,3817) 8126.25,3816.75 8175.75,3816.75 U16.14@8176,3817
  Layer 2 w8: v2(6077,4045) 6278.5,4246.5 7284.59,4246.5 7524.09,4007 7948.09,4007 8013,3942.09 8013,3927 8118,3822 8118.29,3822 8123.29,3817 v1(8126,3817)
  Layer 8 w8: U33.10@5240.05,1622.7 5240.11,1622.64 5240.11,1605.89 v1(5251,1595)
CLLLC_SEC_LEG2_H: J26.54 R65.1 | length 6534.3
  Layer 1 w8: v1(5387.63,75.6) 5334.85,128.38 5334.85,200.85 5491.77,357.77 v2@5491.77,1415.89 ; v2(5769,3088) 5812.87,3088 J26.54@5813.27,3087.6 ; v1(8056,533) 8056,561 R65.1@8059,564
  Layer 2 w8: v1(5387.63,75.6) 5404.63,58.6 5416.4,58.6 5446,29 7829,29 7992.77,192.77 7992.77,470.77 v1@8056,534 ; v2(5493.1,1415.89) 5564.56,1415.89 5693.77,1545.1 5693.77,1859.26 5729,1894.49 5729,2208.59 5750.01,2229.6 5769.6,2229.6 5857.6,2317.6 5893.58,2317.6 5901.77,2325.78 5901.77,2344.1 5845,2400.87 5845,2938.25 5769,3014.25 v2(5769,3088)
CLLLC_SEC_LEG2_H_TEMP: U22.14 U33.9 | length 4627.3
  Layer 1 w8: v1(8145,521) 8145.75,520.25 8197.75,520.25 U22.14@8199,519
  Layer 7 w8: v1(5329.96,1584.87) 5329.96,1582.16 5324.77,1576.97 5324.77,1524.26 5297.92,1497.41 5297.92,1403.94 5294.29,1400.31 5294.29,364.36 5305.12,353.53 5307.57,353.53 5604.09,57 7682,57 7712.5,87.5 7826.5,87.5 7960,221 7960,345 8121.5,506.5 8134.09,519.09 8143.09,519.09 v1(8145,521)
  Layer 8 w8: U33.9@5255.8,1622.7 5255.8,1614.95 5257.25,1613.5 5258.66,1613.5 5287.3,1584.87 v1(5329.96,1584.87)
CLLLC_SEC_LEG2_L: J26.56 R60.1 | length 5962
  Layer 1 w8: v1(5387.63,162.05) 5387.63,203.54 5522.5,338.41 5522.5,1505.49 5522.77,1505.76 5522.77,1510.26 5533.6,1521.1 5538.11,1521.1 5603,1585.99 5603,1795.28 5716.5,1908.78 5716.5,2216.5 5742,2242 v2(5744,2242) ; v2(5734,2488) 5730.27,2491.73 5730.27,2652.86 5730,2653.13 5730,2814.25 5731,2815.25 5731,2898.51 5836.99,3004.5 5845.23,3004.5 5860.27,3019.54 5860.27,3050.16 5854.43,3056 J26.56@5797.27,3056 ; v1(8012,129) R60.1@8037.38,129 8038,129 R60.1@8040,131
  Layer 2 w8: v2(5734,2488) 5793,2429 5793,2365 5747,2319 5747,2317.49 5744.77,2315.26 5744.77,2284.58 5739.77,2279.58 5739.77,2246.23 v2(5744,2242)
  Layer 8 w8: v1(5387.63,162.05) 5520.68,29 7835,29 7934,128 v1@8011,128
CLLLC_SEC_LEG2_L_TEMP: U20.14 U32.9 | length 4149.1
  Layer 1 w8: v2(8143,84) 8143.75,83.25 8185.45,83.25 U20.14@8185.7,83.5
  Layer 2 w8: v1(7920,86) 8139,86 v2@8142,83
  Layer 7 w8: v1(5279.42,1411.6) 5279.42,360.14 5591.8,47.76 5594.24,47.76 5598.5,43.5 7862.5,43.5 7905,86 v1(7920,86)
  Layer 8 w8: U32.9@5258.65,1444.98 5258.65,1437.23 5277.89,1418 5277.89,1413.13 v1(5279.42,1411.6)
CLLLC_SEC_SIDE_SENSE_DIAG: J26.80 J35.4 | length 4354.9
  Layer 1 w8: J26.80@5797.27,2552.06 5791.43,2557.91 5776.02,2557.91 5769.71,2564.22 5744.5,2589.43 5744.5,2698.55 5743.5,2699.55 5743.5,2808.66 5744.5,2809.66 5744.5,2892.92 5842.58,2991 5850.82,2991 5914.5,3054.68 5914.5,3141.31 5916.77,3143.57 5916.77,3190.21 5902.68,3204.3 v1(5902.68,3206.1) ; J35.4@7853.27,4362.6 7853.87,4362 v1(7907,4362)
  Layer 2 w8: v1(6006.85,4197.16) 6006.85,4230.85 6159,4383 7243.55,4383 7524.55,4102 7768.02,4102 7853.02,4187 7853.02,4308.02 v1@7908.35,4363.35
  Layer 7 w8: v1(5902.68,3206.1) 5899.97,3206.1 5894.97,3211.1 5894.77,3211.1 5857.27,3248.6 5857.27,3584.27 5876,3603 5876,4079.91 5947.75,4151.66 6063.09,4151.66 6081.28,4169.85 6081.28,4185.17 6069.21,4197.25 6006.93,4197.25 v1(6006.85,4197.16)
CLLLC_VSEC: C241.1 J26.31 R188.2 | length 148.7
  Layer 1 w20: C241.1@5543.27,3430.02 5545.08,3431.83 v1@5568.27,3431.83 ; v1(5568.27,3432.6) 5569.62,3433.95 J26.31@5663.41,3433.95
  Layer 8 w20: v1(5568.27,3432.6) 5568.27,3422.6 5571.14,3419.72 5571.14,3414.41 5572.95,3412.6 R188.2@5576.89,3412.6 R188.2@5578.27,3412.6
DCLINK: C45.1 C46.1 C47.2 C48.2 C49.1 C50.1 C51.2 C52.2 C67.1 C68.1 C69.2 C70.2 C71.1 C72.1 C73.2 C74.2 C153.1 C154.1 C155.2 C156.2 C157.1 C158.1 C159.2 C160.2 C175.1 C176.1 C177.2 C178.2 C179.1 C180.1 C181.2 C182.2 C223.2 C224.2 C225.2 C226.2 C227.2 C228.2 C229.2 C230.2 C231.2 D10.1 J6.1 J6.2 J8.1 J8.2 J9.1 J9.2 J11.1 J11.2 J38.1 J38.2 Q8.2 Q9.2 R77.1 R96.1 TP8.1 U11.1 U11.2 U11.3 U11.4 U11.5 U11.6 U11.7 U11.8 U11.9 U11.10 U11.11 U11.12 U11.13 U11.14 U11.15 U11.16 U15.1 U15.2 U15.3 U15.4 U15.5 U15.6 U15.7 U15.8 U15.9 U15.10 U15.11 U15.12 U15.13 U15.14 U15.15 U15.16 U37.1 U37.2 U37.3 U37.4 U37.5 U37.6 U37.7 U37.8 U37.9 U37.10 U37.11 U37.12 U37.13 U37.14 U37.15 U37.16 U41.1 U41.2 U41.3 U41.4 U41.5 U41.6 U41.7 U41.8 U41.9 U41.10 U41.11 U41.12 U41.13 U41.14 U41.15 U41.16 | length 11.3
  Layer 4 w50: 4487.27,4371.6 4495.27,4379.6
  other v1: 6045,102 6065,103 6454.65,231.6 6473.27,231.6 6407.41,319.55 6426.03,319.55 6444.65,319.55 6463.27,319.55 6388.79,412.6 6407.41,412.6 6426.03,412.6 6444.65,412.6 6463.27,412.6 6388.79,503.94 6407.41,503.94 6426.03,503.94 6444.65,503.94 6463.27,503.94 6483.27,503.94 6386.79,556.99 6461.27,556.99 6481.27,556.99 6387,578 6470,578 6119.04,716.73 6137.66,716.73 4067.68,1333.65 4095.09,1333.65 4122.5,1333.65 4149.91,1333.65 4177.31,1333.65 4204.72,1333.65 4232.13,1333.65 4259.54,1333.65 4286.95,1333.65 4314.35,1333.65 4341.76,1333.65 4369.17,1333.65 4396.58,1333.65 4423.99,1333.65 4067.68,1354.92 4095.09,1354.92 4122.5,1354.92 4149.91,1354.92 4177.31,1354.92 4204.72,1354.92 4232.13,1354.92 4259.54,1354.92 4286.95,1354.92 4314.35,1354.92 4341.76,1354.92 4369.17,1354.92 4396.58,1354.92 4423.99,1354.92 3396.27,1361.59 3417.54,1361.59 3396.27,1389 3417.54,1389 3396.27,1416.41 3417.54,1416.41 3396.27,1549.26 3417.54,1549.26 3396.27,1576.66 3417.54,1576.66 3396.27,1604.07 3417.54,1604.07 3396.27,1742.78 3417.54,1742.78 5478.27,1757.6 5498.27,1757.6 5918.27,1757.6 5938.27,1757.6 5958.27,1757.6 5978.27,1757.6 5998.27,1757.6 3396.27,1770.19 3417.54,1770.19 3396.27,1797.6 3417.54,1797.6 5458.27,1892.6 5478.27,1892.6 5498.27,1892.6 5958.27,1892.6 5978.27,1892.6 5998.27,1892.6 5965.27,1991.6 5985.27,1991.6 6005.27,1991.6 5468,2023 5488,2023 4021.5,2489.98 4048.91,2489.98 4076.32,2489.98 4103.73,2489.98 4131.14,2489.98 4158.54,2489.98 4185.95,2489.98 4213.36,2489.98 4240.77,2489.98 4268.18,2489.98 4295.59,2489.98 4322.99,2489.98 4350.4,2489.98 4377.81,2489.98 4021.5,2511.26 4048.91,2511.26 4076.32,2511.26 4103.73,2511.26 4131.14,2511.26 4158.54,2511.26 4185.95,2511.26 4213.36,2511.26 4240.77,2511.26 4268.18,2511.26 4295.59,2511.26 4322.99,2511.26 4350.4,2511.26 4377.81,2511.26 5458.27,2707.6 5478.27,2707.6 5498.27,2707.6 5978.27,2707.6 5998.27,2707.6 5978.27,2837.6 5998.27,2837.6 5458.27,2842.6 5478.27,2842.6 5498.27,2842.6 5962.27,2957.6 5982.27,2957.6 5458.27,2977.6 5478.27,2977.6 5498.27,2977.6 5958.27,2982.6 5978.27,2982.6 3186.27,3191.59 3207.54,3191.59 3186.27,3219 3207.54,3219 3186.27,3246.41 3207.54,3246.41 3186.27,3379.26 3207.54,3379.26 3186.27,3406.66 3207.54,3406.66 3186.27,3434.07 3207.54,3434.07 3186.27,3569.78 3207.54,3569.78 6048.27,3590.47 6068.56,3590.47 7166.27,3594.29 7187.54,3594.29 3186.27,3597.19 3207.54,3597.19 6068.56,3608.81 7166.27,3621.7 7187.54,3621.7 3186.27,3624.6 3207.54,3624.6 4060.22,3625.74 4087.63,3625.74 4115.04,3625.74 4142.45,3625.74 4169.85,3625.74 4197.26,3625.74 4224.67,3625.74 4252.08,3625.74 4279.49,3625.74 4306.89,3625.74 4334.3,3625.74 4361.71,3625.74 4389.12,3625.74 4416.53,3625.74 6068.56,3627.15 6068.56,3645.49 7166.27,3649.11 7187.54,3649.11 6068.56,3663.83 7166.27,3676.52 7187.54,3676.52 6068.56,3682.17 4132.04,3696.46 4159.45,3696.46 4186.85,3696.46 4214.26,3696.46 4241.67,3696.46 4269.08,3696.46 4296.49,3696.46 4323.89,3696.46 4351.3,3696.46 4378.71,3696.46 4406.12,3696.46 4433.53,3696.46 6068.56,3700.51 7166.27,3703.92 7187.54,3703.92 6068.56,3718.85 7166.27,3731.33 7187.54,3731.33 6068.56,3737.19 6068.56,3755.53 7166.27,3758.74 7187.54,3758.74 6048.27,3773.87 6068.56,3773.87 7166.27,3786.15 7187.54,3786.15 7166.27,3813.56 7187.54,3813.56 7166.27,3840.97 7187.54,3840.97 5977.27,3861.57 5996.27,3861.57 6015.27,3861.57 6034.27,3861.57 7166.27,3868.37 7187.54,3868.37 7166.27,3895.78 7187.54,3895.78 7166.27,3923.19 7187.54,3923.19 5996.27,3962.14 6015.27,3962.14 6034.27,3962.14
EARTH: C216.2 C217.2 C221.1 C222.1 C234.1 C235.2 J33.1 MP1.1 MP1.2 MP1.3 MP1.4 | length 53.9
  Layer 8 w50: MP1.1@938.37,4329.72 924.46,4315.81 MP1.1@948.68,4291.6
ERRORSTS: R22.1 R84.2 R90.2 U1.2 | length 5443.4
  Layer 2 w8: v1@5716,2260 5716,2264.71 5726.27,2274.97 5726.27,2285.18 5731.27,2290.18 5731.27,2320.85 5733.5,2323.09 5733.5,2346.98 5716,2364.48 5716,2489.09 5831.5,2604.59 5831.5,2932.66 5755.5,3008.66 5755.5,3487.5 5748,3495 v1(5748,3533)
  Layer 7 w8: v1(5282.49,3728.08) 5235.92,3728.08 5176,3788 5176,3905.33 v1(5343.27,4072.6) ; v1(5354.02,3728.08) 5356.72,3728.08 5361.12,3723.68 5363.32,3723.68 5479,3608 5479,3263 5504,3238 5560,3238 5690.39,3368.39 5690.39,3535.7 5702.69,3548 5733,3548 v1(5748,3533) ; v1(5558.27,262.6) 5633.27,262.6 5723.44,352.77 5723.44,664.92 v1(5748.27,689.75)
  Layer 8 w8: v1(5282.49,3728.08) v1(5354.02,3728.08) ; R22.1@5323.27,4172.6 5325.83,4172.6 5343.26,4155.17 U1.2@5343.26,4118 v1(5343.27,4072.6) ; v1(5558.27,262.6) 5608.27,212.6 5663.27,212.6 R84.2@5668.27,217.6 ; R90.2@5711.77,2227.6 5715,2230.83 v1(5715,2261) ; R90.2@5714.02,2225.35 5709.57,2220.9 5709.57,2183.88 5634,2108.32 5634,1529 5798.77,1364.23 5798.77,782.97 5748.27,732.47 v1(5748.27,689.75)
FAULT_H_A: U10.5 U11.46 | length 362.6
  Layer 1 w8: v2(7181.69,4059.9) 7181.69,4096.69 U10.5@7182,4097
  Layer 2 w8: v1@6922,4028 6922,4027 6939.5,4009.5 7131.3,4009.5 v2(7181.69,4059.9)
  Layer 8 w8: v1(6921,4028) 6921.38,4027.62 U11.46@6921.38,3991.62
FAULT_H_B: U14.5 U15.46 | length 867.5
  Layer 1 w10: U14.5@6162.57,237.05 6163.61,236 v2(6203,236)
  Layer 2 w10: v2(6203,236) 6170,203 6170,172.17 6222.67,119.5 6724.5,119.5 6786.5,181.5 6808.08,181.5 6819.5,192.92 6819.5,193.34 6825,198.84 v1(6825,201)
  Layer 8 w10: U15.46@6823.27,234.6 U15.46@6826.03,237.36 ; v1(6825,201) 6825.52,201.52 6825.52,232.48 U15.46@6825,233 ; U15.46@6825.52,232.78 U15.46@6826.03,233.3
FAULT_H_C: R214.2 U19.46 | length 2550.2
  Layer 1 w12: R214.2@8498,4317 v2(8525,4317)
  Layer 2 w12: v2@8523,4318 8503,4318 8485,4300 8485,4142.33 8523,4104.33 8523,4069.74 8572.14,4020.6 8646.18,4020.6 8673.28,3993.5 9507.83,3993.5 9713.51,3787.83 ccw(c9844.57,3838.57) 9747.31,3737.12 10156.83,3344.5 10306.5,3344.5 10310.01,3340.99 10331,3320 10331,3248 v1@10333,3246
  Layer 8 w10: v1@10334,3247 10331.95,3249.05 10331.95,3277.98 U19.46@10331.91,3278.02 U19.46@10334.78,3280.9
  Layer 8 w12: U19.46@10331,3281 U19.46@10331.45,3281.45
  other v1: 10332,3246
FAULT_H_D: R219.2 U23.46 | length 1987.5
  Layer 1 w10: v2(8548,588) 8548,606 R219.2@8549,607
  Layer 2 w10: v2@8548,589 8536.5,577.5 8513.98,577.5 8499,562.52 8499,526.08 8518.08,507 8580,507 8692.77,619.77 8692.77,642.92 8734.19,684.35 8734.27,684.35 8747.92,698 9484,698 9944.97,1158.97 9944.97,1188.39 9982.58,1226 v3@9984,1226
  Layer 8 w10: U23.46@9980.33,1180.19 9983.2,1183.06 U23.46@9983.2,1195.86 ; U23.46@9984,1195 9983.6,1195.4 9983.6,1227.6 v3(9984,1228)
FAULT_H_PFC_1: U36.5 U37.46 | length 437.9
  Layer 1 w10: v2(4756.52,1734.53) 4786.47,1734.53 U36.5@4787,1734
  Layer 2 w10: v1@4493,1687 4494.71,1685.29 4505.71,1685.29 4565,1626 4720.16,1626 4756.52,1662.36 v2(4756.52,1734.53)
  Layer 8 w10: U37.46@4463.02,1687.02 4493.91,1687.02 v1(4494.12,1686.82)
FAULT_H_PFC_2: U40.5 U41.46 | length 517.4
  Layer 1 w8: U40.5@4784,2817 v2(4820,2817)
  Layer 2 w8: v1@4420,2758 4420.58,2758 4434.48,2744.1 4513.93,2744.1 4515.83,2746 4749,2746 v2(4820,2817)
  Layer 8 w8: v1@4417.9,2759 4462.68,2759 U41.46@4463.12,2758.57
  other v1: 4419.49,2759.09
FAULT_L_A: U8.5 U9.46 | length 244
  Layer 1 w12: U8.5@6408.98,3772.34 v2@6408.98,3814.57
  Layer 2 w12: v2@6409,3814 6412.77,3817.77 6412.77,3964.23 v1(6412,3965)
  Layer 8 w12: U9.46@6407,3999 6408.99,3997.01 6408.99,3969.64 6412,3966.62 v1(6412,3965) ; U9.46@6407.11,3983.92 U9.46@6407.11,3996.71
  other v2: 6409.29,3814.57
